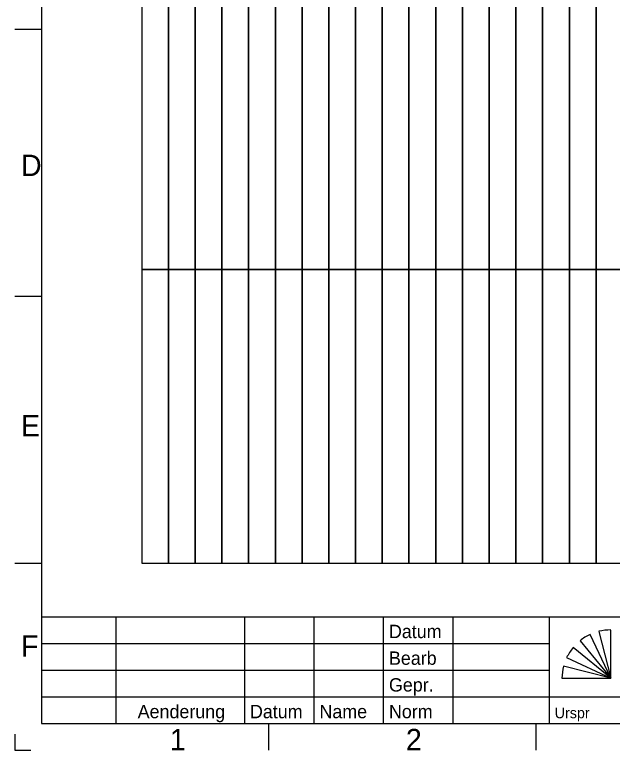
# Model space of a CAD drawing. Extents: x 0 to 395, y 0 to 270.
# Drawn here: x 0 to 111.8, y 0 to 137.7 of the extents above; entities that cross this region are included whole.
import ezdxf

# ---------------------------------------------------------------- set-up
doc = ezdxf.new("R2010")
doc.units = 0
doc.layers.add('30_Graphik', color=7, linetype='Continuous')
doc.layers.add('90_Plankopf', color=7, linetype='Continuous')

msp = doc.modelspace()

# ---------------------------------------------------------------- linework, layer by layer
at = {"layer": '30_Graphik'}
for points in [[(23.75, 185), (23.75, 90), (28.75, 90), (28.75, 185)], [(28.75, 185), (28.75, 90), (33.75, 90), (33.75, 185)], [(33.75, 185), (33.75, 90), (38.75, 90), (38.75, 185)], [(38.75, 185), (38.75, 90), (43.75, 90), (43.75, 185)], [(43.75, 185), (43.75, 90), (48.75, 90), (48.75, 185)], [(48.75, 185), (48.75, 90), (53.75, 90), (53.75, 185)], [(53.75, 185), (53.75, 90), (58.75, 90), (58.75, 185)], [(58.75, 185), (58.75, 90), (63.75, 90), (63.75, 185)], [(63.75, 185), (63.75, 90), (68.75, 90), (68.75, 185)], [(68.75, 185), (68.75, 90), (73.75, 90), (73.75, 185)], [(73.75, 185), (73.75, 90), (78.75, 90), (78.75, 185)], [(78.75, 185), (78.75, 90), (83.75, 90), (83.75, 185)], [(83.75, 185), (83.75, 90), (88.75, 90), (88.75, 185)], [(88.75, 185), (88.75, 90), (93.75, 90), (93.75, 185)], [(93.75, 185), (93.75, 90), (98.75, 90), (98.75, 185)], [(98.75, 185), (98.75, 90), (103.75, 90), (103.75, 185)], [(103.75, 185), (103.75, 90), (108.75, 90), (108.75, 185)], [(108.75, 185), (108.75, 90), (113.75, 90), (113.75, 185)], [(23.75, 90), (23.75, 35), (28.75, 35), (28.75, 90)], [(28.75, 90), (28.75, 35), (33.75, 35), (33.75, 90)], [(33.75, 90), (33.75, 35), (38.75, 35), (38.75, 90)], [(38.75, 90), (38.75, 35), (43.75, 35), (43.75, 90)], [(43.75, 90), (43.75, 35), (48.75, 35), (48.75, 90)], [(48.75, 90), (48.75, 35), (53.75, 35), (53.75, 90)], [(53.75, 90), (53.75, 35), (58.75, 35), (58.75, 90)], [(58.75, 90), (58.75, 35), (63.75, 35), (63.75, 90)], [(63.75, 90), (63.75, 35), (68.75, 35), (68.75, 90)], [(68.75, 90), (68.75, 35), (73.75, 35), (73.75, 90)], [(73.75, 90), (73.75, 35), (78.75, 35), (78.75, 90)], [(78.75, 90), (78.75, 35), (83.75, 35), (83.75, 90)], [(83.75, 90), (83.75, 35), (88.75, 35), (88.75, 90)], [(88.75, 90), (88.75, 35), (93.75, 35), (93.75, 90)], [(93.75, 90), (93.75, 35), (98.75, 35), (98.75, 90)], [(98.75, 90), (98.75, 35), (103.75, 35), (103.75, 90)], [(103.75, 90), (103.75, 35), (108.75, 35), (108.75, 90)], [(108.75, 90), (108.75, 35), (113.75, 35), (113.75, 90)]]:
    msp.add_lwpolyline(points, close=True, dxfattribs=at)
at = {"layer": '90_Plankopf'}
for p, q in [((5, 265), (5, 5)), ((0, 135), (5, 135)), ((0, 85), (5, 85)), ((0, 35), (5, 35)), ((5, 25), (390, 25)), ((19, 5), (19, 25)), ((43, 25), (43, 5)), ((56, 5), (56, 25)), ((69, 5), (69, 25)), ((82, 5), (82, 25)), ((100, 25), (100, 5)), ((109.27, 22.26), (111.48, 13.52)), ((111.48, 13.52), (111.48, 22.51)), ((111.48, 13.52), (107.63, 21.68)), ((5, 20), (100, 20)), ((105.74, 20.52), (111.48, 13.52)), ((111.48, 13.52), (104.43, 19.22)), ((103.24, 17.34), (111.48, 13.52)), ((111.48, 13.52), (102.66, 15.72)), ((5, 15), (100, 15)), ((102.36, 13.52), (111.48, 13.52)), ((5, 10), (100, 10)), ((100, 10), (225, 10)), ((5, 5), (390, 5)), ((47.5, 5), (47.5, 0)), ((97.5, 5), (97.5, 0)), ((0, 3), (0, 0)), ((0, 0), (3, 0))]:
    msp.add_line(p, q, dxfattribs=at)
for centre, start, end in [((111.45, 12.99), 89.8053, 103.1895), ((111.66, 13.05), 115.0126, 128.3968), ((111.82, 13.19), 140.7898, 154.174), ((111.89, 13.37), 165.7222, 179.1064)]:
    msp.add_arc(centre, 9.53, start, end, dxfattribs=at)

# ---------------------------------------------------------------- texts
for s, height, p in [('D', 4, (1.17, 107.5)), ('E', 4, (1.17, 58.75)), ('Datum', 2.5, (70, 21)), ('F', 4, (1.17, 17.5)), ('Bearb', 2.5, (70, 16)), ('Gepr.', 2.5, (70, 11)), ('Aenderung', 2.5, (23, 6)), ('Datum', 2.5, (44, 6)), ('Name', 2.5, (57, 6)), ('Norm', 2.5, (70, 6)), ('Urspr', 2, (101, 6)), ('1', 4, (29, 0)), ('2', 4, (73.17, 0))]:
    msp.add_text(s, height=height, dxfattribs=at).set_placement(p)

doc.saveas('drawing.dxf')
